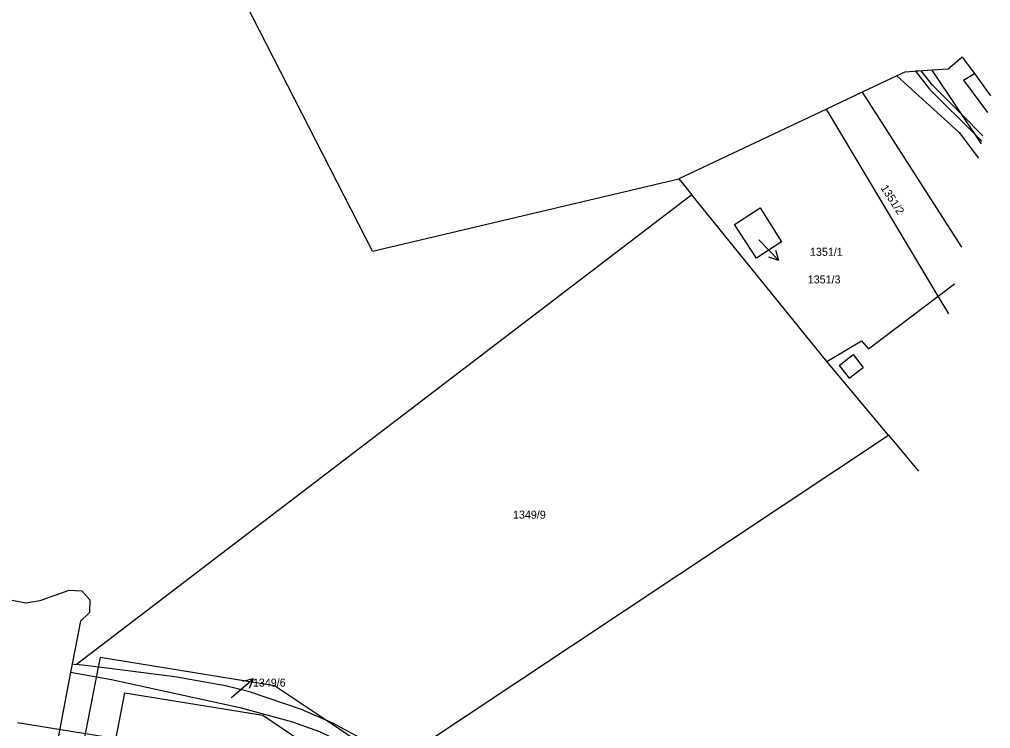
# Model space of a CAD drawing. Extents: x -601602 to -600882, y -1162594 to -1161950.
# Drawn here: x -600985.6 to -600882.5, y -1162273.6 to -1162198.3 of the extents above; entities that cross this region are included whole.
import ezdxf

# ---------------------------------------------------------------- set-up
doc = ezdxf.new("R2010")
doc.units = 0
for name, color, linetype in [('KN_Hranice parcel', 7, 'Continuous'), ('KN_Parcelní čísla', 7, 'Continuous'), ('KN_Pop  PČ popisy', 7, 'Continuous'), ('KN_Vnitřní kresba', 7, 'Continuous'), ('KN_Věcná břemena k části', 7, 'Continuous')]:
    doc.layers.add(name, color=color, linetype=linetype)

# ---------------------------------------------------------------- blocks, each defined once
blk = doc.blocks.new('1029_43')
at = {"layer": 'KN_Pop  PČ popisy'}
for p, q in [((0, 0), (2.27, 1.97)), ((2.27, 1.97), (1.18, 1.69)), ((2.27, 1.97), (1.84, 0.93))]:
    blk.add_line(p, q, dxfattribs=at)
blk = doc.blocks.new('1029_65')
at = {"layer": 'KN_Pop  PČ popisy'}
for p, q in [((0, 0), (2.08, -2.16)), ((2.08, -2.16), (1.03, -1.79)), ((2.08, -2.16), (1.75, -1.09))]:
    blk.add_line(p, q, dxfattribs=at)

msp = doc.modelspace()

# ---------------------------------------------------------------- linework, layer by layer
at = {"layer": 'KN_Hranice parcel'}
for p, q in [((-600885.48, -1162202.29), (-600884.19, -1162204.04)), ((-600884.19, -1162204.04), (-600882.47, -1162206.42)), ((-600896.12, -1162206.03), (-600899.9, -1162207.82)), ((-600896.12, -1162206.03), (-600885.55, -1162222.48)), ((-600899.9, -1162207.82), (-600915.57, -1162215.22)), ((-600888.03, -1162227.67), (-600899.9, -1162207.82)), ((-600948.1, -1162222.9), (-600915.57, -1162215.22)), ((-600915.57, -1162215.22), (-600914.2, -1162216.91)), ((-600914.2, -1162216.91), (-600979.49, -1162266.77)), ((-600899.84, -1162234.61), (-600914.2, -1162216.91)), ((-600888.03, -1162227.67), (-600886.3, -1162226.36)), ((-600895.43, -1162233.27), (-600888.03, -1162227.67)), ((-600893.29, -1162242.43), (-600899.84, -1162234.61)), ((-600945.37, -1162276.99), (-600893.29, -1162242.43)), ((-600893.29, -1162242.43), (-600890.11, -1162246.23)), ((-600979.97, -1162266.71), (-600980.13, -1162267.57)), ((-600979.97, -1162266.71), (-600979.49, -1162266.77)), ((-600980.13, -1162267.57), (-600981.57, -1162275.06))]:
    msp.add_line(p, q, dxfattribs=at)
for points in [[(-600948.1, -1162222.9), (-600975.07, -1162170.16), (-600998.81, -1162133.13)], [(-600885.48, -1162202.29), (-600886.99, -1162203.57), (-600888.68, -1162203.69)], [(-600888.68, -1162203.69), (-600891.58, -1162203.89), (-600892.44, -1162204.3), (-600896.12, -1162206.03)], [(-600883.44, -1162211.49), (-600888.68, -1162203.69)], [(-600904.66, -1162221.89), (-600907.31, -1162223.63), (-600909.64, -1162220.08), (-600906.93, -1162218.3), (-600904.66, -1162221.89)], [(-600886.91, -1162229.54), (-600888.03, -1162227.67)], [(-600899.84, -1162234.61), (-600896.19, -1162232.4), (-600895.43, -1162233.27)], [(-600995.07, -1162264.57), (-600993.91, -1162258.49), (-600984.87, -1162260.22), (-600983.35, -1162259.98), (-600980.3, -1162258.88), (-600978.94, -1162258.95), (-600978.08, -1162259.9), (-600978.12, -1162261.23), (-600979.09, -1162262.15), (-600979.97, -1162266.71)], [(-600945.37, -1162276.99), (-600947.74, -1162275.47), (-600952.3, -1162273), (-600955.63, -1162271.53), (-600961.13, -1162269.66), (-600963.68, -1162269.01), (-600969.05, -1162268.07), (-600976.58, -1162267.13), (-600979.49, -1162266.77)], [(-600980.13, -1162267.57), (-600975.78, -1162268.36), (-600962.15, -1162271.32), (-600956.57, -1162272.84), (-600953.71, -1162273.86), (-600947.53, -1162276.88), (-600946.31, -1162277.62)]]:
    msp.add_lwpolyline(points, dxfattribs=at)
at = {"layer": 'KN_Pop  PČ popisy'}
for p, q in [((-600907.08, -1162221.67), (-600907.03, -1162221.73)), ((-600963.1, -1162270.3), (-600963.03, -1162270.24))]:
    msp.add_line(p, q, dxfattribs=at)
at = {"layer": 'KN_Vnitřní kresba'}
for p, q in [((-600885.33, -1162204.75), (-600884.19, -1162204.04)), ((-600892.44, -1162204.3), (-600885.8, -1162210.32)), ((-600885.33, -1162204.75), (-600882.81, -1162208.18)), ((-600885.8, -1162210.32), (-600883.74, -1162213.03)), ((-600898.53, -1162235.03), (-600897.07, -1162233.88)), ((-600897.07, -1162233.88), (-600896.01, -1162235.23)), ((-600898.53, -1162235.03), (-600897.47, -1162236.38)), ((-600897.47, -1162236.38), (-600896.01, -1162235.23))]:
    msp.add_line(p, q, dxfattribs=at)
at = {"layer": 'KN_Věcná břemena k části'}
for points in [[(-600883.28, -1162210.64), (-600885.5, -1162208.43), (-600888.61, -1162205.33), (-600889.83, -1162203.77), (-600890.43, -1162203.81), (-600888.97, -1162205.69), (-600884.04, -1162210.6), (-600883.4, -1162211.24)], [(-600905.07, -1162324.2), (-600916.57, -1162312.53), (-600919.88, -1162308.07), (-600939.23, -1162281.94), (-600945.99, -1162277.4), (-600952.98, -1162272.7), (-600958.47, -1162269.01), (-600976.98, -1162266.01), (-600977.19, -1162267.06), (-600978.83, -1162275.41), (-600979.42, -1162278.42), (-600976.18, -1162279.06), (-600975.55, -1162275.82), (-600974.36, -1162269.77), (-600959.71, -1162272.15), (-600948.96, -1162279.38), (-600941.55, -1162284.36), (-600921.96, -1162310.82), (-600919.09, -1162314.69), (-600905.83, -1162328.15)], [(-600906.33, -1162330.78), (-600915.04, -1162322.13), (-600923.25, -1162312.42), (-600924.2, -1162311.3), (-600937.66, -1162293.53), (-600941.81, -1162288.8), (-600946.55, -1162284.53), (-600952.04, -1162281.42), (-600952.45, -1162281.19), (-600959.7, -1162278.22), (-600974.17, -1162274.83), (-600985.77, -1162272.97)]]:
    msp.add_lwpolyline(points, dxfattribs=at)

# ---------------------------------------------------------------- block references
at = {"layer": 'KN_Pop  PČ popisy'}
for name, p in [('1029_65', (-600907.03, -1162221.73)), ('1029_43', (-600963.03, -1162270.24))]:
    msp.add_blockref(name, p, dxfattribs=at)

# ---------------------------------------------------------------- texts
at = {"layer": 'KN_Parcelní čísla'}
msp.add_text('1351/2', height=0.85, rotation=303, dxfattribs=at).set_placement((-600894.18, -1162216.19))
for s, p in [('1351/1', (-600901.64, -1162223.39)), ('1351/3', (-600901.88, -1162226.32)), ('1349/9', (-600933.17, -1162251.29)), ('1349/6', (-600960.78, -1162269.11))]:
    msp.add_text(s, height=0.85, dxfattribs=at).set_placement(p)

doc.saveas('drawing.dxf')
